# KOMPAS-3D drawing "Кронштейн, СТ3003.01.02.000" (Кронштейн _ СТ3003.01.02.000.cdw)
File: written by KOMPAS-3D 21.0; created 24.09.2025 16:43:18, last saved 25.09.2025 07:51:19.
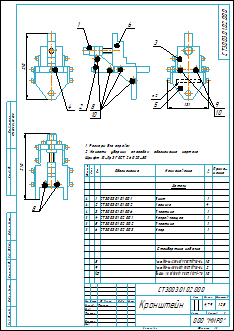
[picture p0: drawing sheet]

Sheet 1: A3, portrait

Document properties: Полное имя файла: ..\..\3D\Кронштейн _ СТ3003.01.02.000\Кронштейн _ СТ3003.01.02.000.a3d; Масса: 4.787723

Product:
- Part/product: Кронштейн  | designation СТ3003.01.02.000
    Масса: 4.787723
    Форматы листов документа: A3
  - Component [standard]: Шайба A.8.01.10.019 ГОСТ 11371-78  | qty 10  | pos. 10  | Масса: 0.001828; Раздел спецификации: Стандартные изделия; Рассекать на разрезах: no
  - Component [standard]: Винт М8-6gx25.56.019 ГОСТ 11738-84  | qty 10  | pos. 8  | Материал: Сталь 30 ГОСТ 1050-2013 (density 1000 kg/m3); Масса: 0.01513; Раздел спецификации: Стандартные изделия; Рассекать на разрезах: no
  - Component [detail]: Косынка  | designation СТ3003.01.01.002  | qty 4  | pos. 2  | Материал: Лист$dБ-ПН-НО-6 ГОСТ 19903-2015;Ст3сп ГОСТ 14637-89$ (density 7850 kg/m3); Масса: 0.116828; Форматы листов документа: A4; source file: ..\..\3D\Кронштейн _ СТ3003.01.01.000\Косынка _ СТ3003.01.01.002.m3d
  - Component [detail]: Винт  | designation СТ3003.01.01.001  | pos. 1  | Материал: Круг$d30 ГОСТ 2590-2006;Ст3сп ГОСТ 535-2005$ (density 7850 kg/m3); Масса: 0.311599; Форматы листов документа: A4; additional columns: 110; source file: ..\..\3D\Кронштейн _ СТ3003.01.01.000\Винт _ СТ3003.01.01.001.m3d, ..\Кронштейн _ СТ3003.01.01.000\Винт _ СТ3003.01.01.001.cdw
  - Component [detail]: Упор  | designation СТ3003.01.02.003  | pos. 6  | Материал: Сталь 45  ГОСТ 1050-2013 (density 7810 kg/m3); Масса: 0.784266; Форматы листов документа: A3; source file: ..\..\3D\Кронштейн _ СТ3003.01.02.000\Упор _ СТ3003.01.02.003.m3d
  - Component [detail]: Пластина  | designation СТ3003.01.01.006  | pos. 3  | Материал: Лист$dБ-ПН-НО-16 ГОСТ 19903-2015;Ст3сп ГОСТ 14637-89$ (density 7850 kg/m3); Масса: 0.669577; Форматы листов документа: A4; source file: ..\..\3D\Кронштейн _ СТ3003.01.01.000\Пластина _ СТ3003.01.01.006.m3d
  - Component [detail]: Направляющая  | designation СТ3003.01.02.001  | pos. 4  | Материал: Сталь 45  ГОСТ 1050-2013 (density 7810 kg/m3); Масса: 1.56864; Форматы листов документа: A3; source file: ..\..\3D\Кронштейн _ СТ3003.01.02.000\Направляющая _ СТ3003.01.02.001.m3d, Направляющая _ СТ3003.01.02.001.cdw
  - Component [detail]: Пластина  | designation СТ3003.01.02.002  | pos. 5  | Материал: Лист$dБ-ПН-НО-16 ГОСТ 19903-2015;Ст3сп ГОСТ 14637-89$ (density 7850 kg/m3); Масса: 0.780129; Форматы листов документа: A3; source file: ..\..\3D\Кронштейн _ СТ3003.01.02.000\Пластина _ СТ3003.01.02.002.m3d
  - Component [standard]: Винт М8-6gx35.56.019 ГОСТ 11738-84  | qty 2  | pos. 9  | Материал: Сталь 30 ГОСТ 1050-2013 (density 1000 kg/m3); Масса: 0.01831; Раздел спецификации: Стандартные изделия; Рассекать на разрезах: no

Title block, sheet 1: Наименование: Кронштейн; designation: СТ3003.01.02.000; Масса: 4,79; Количество листов документа: 1; organisation: ООО "МИРО"; Форматы листов документа: A3; stored path: C:\Users\1\Yandex.Disk\Документы\Новая папка\Стапель №2\Стапель _ СТ3003.00.00.000\Опора _ СТ3003.01.00.000\2D\Кронштейн _ СТ3003.01.02.000\Кронштейн _ СТ3003.01.02.000.cdw; Разработал: Тимонин

Views: Вид 1, Справа, Проекционный вид 3, Проекционный вид 4
Referenced files in C:\Users\1\Yandex.Disk\Документы\Новая папка\Стапель №2\Стапель _ СТ3003.00.00.000\Опора _ СТ3003.01.00.000\3D\Кронштейн _ СТ3003.01.02.000\: Кронштейн _ СТ3003.01.02.000.a3d, Направляющая _ СТ3003.01.02.001.m3d, Упор _ СТ3003.01.02.003.m3d, Пластина _ СТ3003.01.02.002.m3d
Referenced files in C:\Users\1\Yandex.Disk\Документы\Новая папка\Стапель №2\Стапель _ СТ3003.00.00.000\Опора _ СТ3003.01.00.000\2D\Кронштейн _ СТ3003.01.02.000\: Направляющая _ СТ3003.01.02.001.cdw
Referenced files in C:\Users\1\Yandex.Disk\Документы\Новая папка\Стапель №2\Стапель _ СТ3003.00.00.000\Опора _ СТ3003.01.00.000\3D\Кронштейн _ СТ3003.01.01.000\: Косынка _ СТ3003.01.01.002.m3d, Винт _ СТ3003.01.01.001.m3d, Пластина _ СТ3003.01.01.006.m3d
Referenced files in C:\Users\1\Yandex.Disk\Документы\Новая папка\Стапель №2\Стапель _ СТ3003.00.00.000\Опора _ СТ3003.01.00.000\2D\Кронштейн _ СТ3003.01.01.000\: Винт _ СТ3003.01.01.001.cdw
Referenced files in C:\Program Files\ASCON\KOMPAS-3D v21\Libs\PartLib\DATA\VAULT\Methods\Kompas\3D\: PLib_Screw_GOST_11738_1500.m3d, PLib_Washer_1_712.m3d
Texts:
  Винт М8-6gx25.56.019 ГОСТ 11738-84
  Крепежное изделие ГОСТ
  Винт
  ГОСТ
  Шайба A.8.01.10.019 ГОСТ 11371-78
  Шайба
  СТ3003.01.02.001
  Направляющая
  СТ3003.01.01.002
  Косынка
  СТ3003.01.02.003
  Упор
  СТ3003.01.01.001
  Винт М8-6gx35.56.019 ГОСТ 11738-84
  СТ3003.01.02.002
  Пластина
  СТ3003.01.01.006
  СТ3003.01.00.000
  СТ3003.01.02.002 Пластина
  СТ3003.01.02.001 Направляющая
  СТ3003.01.01.006 Пластина
  СТ3003.01.01.002 Косынка
  СТ3003.01.02.003 Упор
  СТ3003.01.01.001 Винт
  СТ3003.01.02.000 Кронштейн
Dimensions and other numbers on the sheet: 210; 4; 1; 2; 6; 8; 10; 131; 5; 3; 9; 56; 40Х; 019; 01; 1:2,5; 4,79

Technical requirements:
  Размеры для справок.
  Нанести ударным способом обозначение чертежа.
  Шрифт 10-Пр3  ГОСТ 26.020-80.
